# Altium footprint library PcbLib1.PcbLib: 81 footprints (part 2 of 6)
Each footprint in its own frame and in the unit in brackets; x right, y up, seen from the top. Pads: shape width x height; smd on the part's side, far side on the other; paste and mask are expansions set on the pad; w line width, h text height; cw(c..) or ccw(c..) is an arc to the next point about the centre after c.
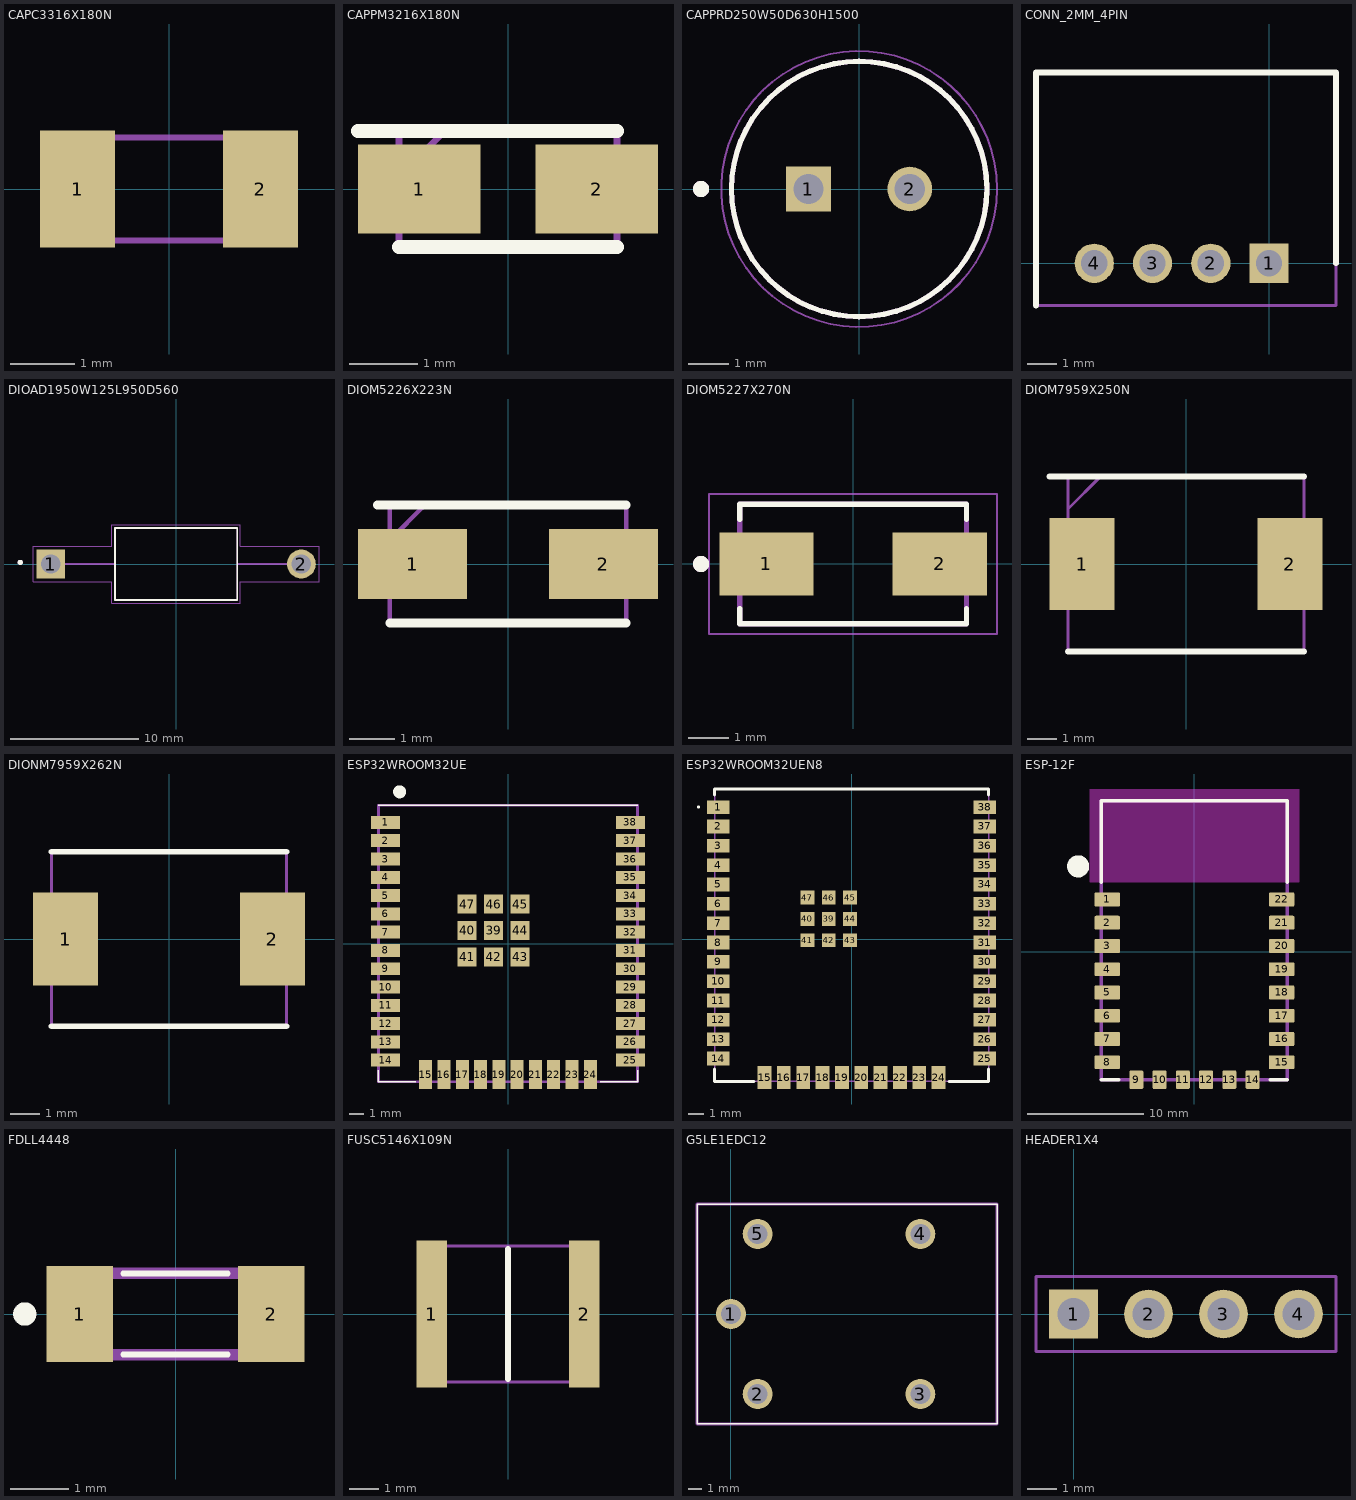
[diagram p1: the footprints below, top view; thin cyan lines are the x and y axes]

## CAPC3316X180N [mm] "1206"
pads (2):
  rect 1.17x1.82 smd: 1(-1.42,0) 2(1.42,0)
Mechanical 13:
  lines w0.1: -1.65,-0.8 1.65,-0.8 1.65,0.8 -1.65,0.8 -1.65,-0.8
3D body "1206GC181KAT2A.stp": height 1.8, standoff 0, extent -1.65,-0.8 1.65,0.8

## CAPPM3216X180N [mm]
pads (2):
  rect 1.8x1.3 smd: 1(-1.3,0) 2(1.3,0)
Top Overlay:
  lines w0.2: -2.2,0.85 1.6,0.85 ; -1.6,-0.85 1.6,-0.85
Mechanical 13:
  lines w0.1: -1.6,0.175 -0.95,0.825 ; -1.6,-0.825 1.6,-0.825 1.6,0.825 -1.6,0.825 -1.6,-0.825
3D body "TAJA106K016RNJ.stp": height 1.8, standoff 0, extent -1.6,-0.825 1.6,0.825

## CAPPRD250W50D630H1500 [mm]
pads (2):
  rect 1.1x1.1 / inner round 1.1 / far side rect 1.1x1.1 hole 0.75: 1(-1.25,0)
  round 1.1 hole 0.75: 2(1.25,0)
Top Overlay:
  circle w0.127: c0,0 r3.15
  circle w0.2: c-3.9,0 r0.1
Mechanical 13:
  circle w0.127: c0,0 r3.15
  circle w0.2: c-3.9,0 r0.1
Mechanical 15:
  circle w0.05: c0,0 r3.4
3D body "step_temp.STEP": height 15, standoff -17, extent -3.15,-3.15 3.15,3.15

## CONN_2MM_4PIN [mm]
pads (4):
  rect 1.35x1.35 hole 0.9: 1(0,0)
  round 1.35 hole 0.9: 2(-2,0) 3(-4,0) 4(-6,0)
Top Overlay:
  lines w0.2: -8,-1.45 -8,6.55 2.3,6.55 2.3,0
Mechanical 13:
  lines w0.1: -8,-1.45 2.3,-1.45 2.3,6.55 -8,6.55 -8,-1.45
3D body "440055-4.stp": height 4.95, standoff -3.39, extent -7.97,-1.3 2.03,6.4

## DIOAD1950W125L950D560 [mm]
pads (2):
  rect 2.25x2.25 hole 1.5: 1(-9.75,0)
  round 2.25 hole 1.5: 2(9.75,0)
Top Overlay:
  circle w0.2: c-12.12,0.12 r0.1
  lines w0.127: -4.75,-2.8 4.75,-2.8 4.75,2.8 -4.75,2.8 -4.75,-2.8
Mechanical 13:
  circle w0.2: c-12.12,0.12 r0.1
  lines w0.127: -8.625,0 -4.75,0 ; 4.75,0 8.625,0 ; -4.75,0 -4.75,-2.8 4.75,-2.8 4.75,2.8 -4.75,2.8 -4.75,0
Mechanical 15:
  lines w0.05: -11.125,-1.375 -11.125,1.375 -5,1.375 -5,3.05 5,3.05 5,1.375 11.125,1.375 11.125,-1.375 5,-1.375 5,-3.05 -5,-3.05 -5,-1.375 -11.125,-1.375
3D body "SB560.STEP": height 5.3, standoff -17, extent -10.375,-2.65 10.775,2.65

## DIOM5226X223N [mm]
pads (2):
  rect 2.4x1.55 smd: 1(-2.1,0) 2(2.1,0)
Top Overlay:
  lines w0.2: -2.875,1.3 2.6,1.3 ; -2.6,-1.3 2.6,-1.3
Mechanical 13:
  lines w0.1: -2.6,0.525 -1.825,1.3 ; -2.6,-1.3 2.6,-1.3 2.6,1.3 -2.6,1.3 -2.6,-1.3
3D body "STPS140A.stp": height 2.23, standoff 0, extent -2.6,-1.3 2.6,1.3

## DIOM5227X270N [mm]
pads (2):
  rect 2.33x1.56 smd: 1(-2.14,0) 2(2.14,0)
Top Overlay:
  circle w0.2: c-3.755,0 r0.1
  lines w0.127: -2.8,-1.1 -2.8,-1.475 2.8,-1.475 2.8,-1.1 ; -2.8,1.1 -2.8,1.475 2.8,1.475 2.8,1.1
Mechanical 13:
  circle w0.2: c-3.755,0 r0.1
  lines w0.127: -2.8,-1.475 -2.8,1.475 2.8,1.475 2.8,-1.475 -2.8,-1.475
Mechanical 15:
  lines w0.05: -3.555,-1.725 3.555,-1.725 3.555,1.725 -3.555,1.725 -3.555,-1.725
3D body "S1M--3DModel-STEP-56544.STEP": height 2.7, standoff 0, extent -2.675,-1.362 2.525,1.362

## DIOM7959X250N [mm]
pads (2):
  rect 2.2x3.1 smd: 1(-3.5,0) 2(3.5,0)
Top Overlay:
  lines w0.2: -4.6,2.952 3.97,2.952 ; -3.97,-2.952 3.97,-2.952
Mechanical 13:
  lines w0.1: -3.97,1.852 -2.87,2.952 ; -3.97,-2.952 3.97,-2.952 3.97,2.952 -3.97,2.952 -3.97,-2.952
3D body "B550C-13-F.stp": height 2.5, standoff 0, extent -3.97,-2.953 3.97,2.953

## DIONM7959X262N [mm]
pads (2):
  rect 2.2x3.15 smd: 1(-3.5,0) 2(3.5,0)
Top Overlay:
  lines w0.2: -3.97,-2.952 3.97,-2.952 ; -3.97,2.952 3.97,2.952
Mechanical 13:
  lines w0.1: -3.97,-2.952 -3.97,2.952 3.97,2.952 3.97,-2.952 -3.97,-2.952
3D body "SMCJ33CA-E3_57T.stp": height 2.62, standoff 0, extent -3.97,-2.953 3.97,2.953

## ESP32WROOM32UE [mm]
pads (47):
  rect 2x0.9 smd: 1(-8.5,8.41) 2(-8.5,7.14) 3(-8.5,5.87) 4(-8.5,4.6) 5(-8.5,3.33) 6(-8.5,2.06) 7(-8.5,0.79) 8(-8.5,-0.48) 9(-8.5,-1.75) 10(-8.5,-3.02) 11(-8.5,-4.29) 12(-8.5,-5.56) 13(-8.5,-6.83) 14(-8.5,-8.1) 25(8.5,-8.1) 26(8.5,-6.83) 27(8.5,-5.56) 28(8.5,-4.29) 29(8.5,-3.02) 30(8.5,-1.75) 31(8.5,-0.48) 32(8.5,0.79) 33(8.5,2.06) 34(8.5,3.33) 35(8.5,4.6) 36(8.5,5.87) 37(8.5,7.14) 38(8.5,8.41)
  rect 0.9x2 smd: 15(-5.715,-9.1) 16(-4.445,-9.1) 17(-3.175,-9.1) 18(-1.905,-9.1) 19(-0.635,-9.1) 20(0.635,-9.1) 21(1.905,-9.1) 22(3.175,-9.1) 23(4.445,-9.1) 24(5.715,-9.1)
  rect 1.33x1.33 smd: 39(-1,0.91) 40(-2.835,0.91) 41(-2.835,-0.925) 42(-1,-0.925) 43(0.835,-0.925) 44(0.835,0.91) 45(0.835,2.745) 46(-1,2.745) 47(-2.835,2.745)
Top Overlay:
  lines w0.1: -9,-8.8 -9,-9.6 -6.4,-9.6 ; -9,9.6 9,9.6 ; 6.4,-9.6 9,-9.6 9,-8.8
  lines w0.5: -7.525,10.332 cw(c-7.525,10.532) -7.525,10.732 cw(c-7.525,10.532) -7.525,10.332
Mechanical 13:
  lines w0.2: -9,-9.6 9,-9.6 9,9.6 -9,9.6 -9,-9.6
3D body "ESP32-WROOM-32UE__16MB_.stp": height 3.2, standoff 0, extent -9,-9.6 9,9.6

## ESP32WROOM32UEN8 [mm]
pads (47):
  rect 1.5x0.9 smd: 1(-8.75,8.66) 2(-8.75,7.39) 3(-8.75,6.12) 4(-8.75,4.85) 5(-8.75,3.58) 6(-8.75,2.31) 7(-8.75,1.04) 8(-8.75,-0.23) 9(-8.75,-1.5) 10(-8.75,-2.77) 11(-8.75,-4.04) 12(-8.75,-5.31) 13(-8.75,-6.58) 14(-8.75,-7.85) 25(8.75,-7.85) 26(8.75,-6.58) 27(8.75,-5.31) 28(8.75,-4.04) 29(8.75,-2.77) 30(8.75,-1.5) 31(8.75,-0.23) 32(8.75,1.04) 33(8.75,2.31) 34(8.75,3.58) 35(8.75,4.85) 36(8.75,6.12) 37(8.75,7.39) 38(8.75,8.66)
  rect 0.9x1.5 smd: 15(-5.715,-9.1) 16(-4.445,-9.1) 17(-3.175,-9.1) 18(-1.905,-9.1) 19(-0.635,-9.1) 20(0.635,-9.1) 21(1.905,-9.1) 22(3.175,-9.1) 23(4.445,-9.1) 24(5.715,-9.1)
  rect 0.9x0.9 smd: 39(-1.5,1.32) 40(-2.9,1.32) 41(-2.9,-0.08) 42(-1.5,-0.08) 43(-0.1,-0.08) 44(-0.1,1.32) 45(-0.1,2.72) 46(-1.5,2.72) 47(-2.9,2.72)
Top Overlay:
  lines w0.1: -10.1,8.66 ccw(c-10.05,8.66) -10,8.66 ccw(c-10.05,8.66) -10.1,8.66
  lines w0.2: -9,-8.55 -9,-9.35 -6.4,-9.35 ; -9,9.45 -9,9.85 9,9.85 9,9.45 ; 6.4,-9.35 9,-9.35 9,-8.55
Mechanical 13:
  lines w0.1: -9,-9.35 -9,9.85 9,9.85 9,-9.35 -9,-9.35
3D body "ESP32-WROOM-32UE__16MB_.stp": height 3.2, standoff 0, extent -8.983,-9.346 9.017,9.854

## ESP-12F [mm]
pads (22):
  rrect20% 2.2x1.2 smd: 1(-7.5,4.5) 2(-7.5,2.5) 3(-7.5,0.5) 4(-7.5,-1.5) 5(-7.5,-3.5) 6(-7.5,-5.5) 7(-7.5,-7.5) 8(-7.5,-9.5) 15(7.5,-9.5) 16(7.5,-7.5) 17(7.5,-5.5) 18(7.5,-3.5) 19(7.5,-1.5) 20(7.5,0.5) 21(7.5,2.5) 22(7.5,4.5)
  rrect20% 1.2x1.6 smd: 9(-5,-11) 10(-3,-11) 11(-1,-11) 12(1,-11) 13(3,-11) 14(5,-11)
Top Overlay:
  circle w1: c-10,7.35 r0.45
  lines w0.3: -8,-11 -6.5,-11 ; -8,6 -8,13 8,13 8,6 ; 6.5,-11 8,-11
Keep-Out Layer:
  region: 9,6 -9,6 -9,14 9,14
  region: 9,6 -9,6 -9,14 9,14
Mechanical 13:
  lines w0.3: -8,-11 8,-11 8,13 -8,13 -8,-11
3D body "ESP-12S--3DModel-STEP-56544.STEP": height 3.2, standoff 0, extent -8,-11 8,13

## FDLL4448 [mm]
pads (2):
  rect 1.15x1.65 smd: 1(-1.65,0) 2(1.65,0)
Top Overlay:
  lines w0.1: -0.9,-0.7 0.9,-0.7 ; -0.9,0.7 0.9,0.7
  lines w0.2: -2.6,-0.1 cw(c-2.6,0) -2.6,0.1 cw(c-2.6,0) -2.6,-0.1
Mechanical 13:
  lines w0.2: -1.7,-0.7 -1.7,0.7 1.7,0.7 1.7,-0.7 -1.7,-0.7
3D body "FDLL4148.stp": height 1.5, standoff 0, extent -1.88,-0.75 1.72,0.75

## FUSC5146X109N [mm]
pads (2):
  rect 1.02x4.94 smd: 1(-2.565,0) 2(2.565,0)
Top Overlay:
  lines w0.2: 0,-2.188 0,2.188
Mechanical 13:
  lines w0.1: -2.54,-2.288 2.54,-2.288 2.54,2.288 -2.54,2.288 -2.54,-2.288
3D body "MF-SMDF050-2.stp": height 1.09, standoff 0, extent -2.54,-2.288 2.54,2.288

## G5LE1EDC12 [mm]
pads (5):
  round 2.25 hole 1.5: 1(0,0) 2(2,-6) 3(14.2,-6) 4(14.2,6) 5(2,6)
Top Overlay:
  lines w0.1: -2.55,-8.25 -2.55,8.25 19.95,8.25 19.95,-8.25 -2.55,-8.25
Mechanical 13:
  lines w0.2: -2.55,-8.25 -2.55,8.25 19.95,8.25 19.95,-8.25 -2.55,-8.25
3D body "G5LE-1-E-DC24.stp": height 19.1, standoff -5, extent -2.55,-8.25 19.95,8.25

## HEADER1X4 [mm]
pads (4):
  rect 1.65x1.65 hole 1.1: 1(0,0)
  round 1.65 hole 1.1: 2(2.54,0) 3(5.08,0) 4(7.62,0)
Mechanical 13:
  lines w0.1: -1.27,-1.27 8.89,-1.27 8.89,1.27 -1.27,1.27 -1.27,-1.27
3D body "m20-9990246_asm.stp": height 8.7, standoff -2.98, extent 3.81,-1.27 8.89,1.27
3D body "m20-9990246_asm.stp": height 8.7, standoff -2.98, extent -1.27,-1.27 3.81,1.27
